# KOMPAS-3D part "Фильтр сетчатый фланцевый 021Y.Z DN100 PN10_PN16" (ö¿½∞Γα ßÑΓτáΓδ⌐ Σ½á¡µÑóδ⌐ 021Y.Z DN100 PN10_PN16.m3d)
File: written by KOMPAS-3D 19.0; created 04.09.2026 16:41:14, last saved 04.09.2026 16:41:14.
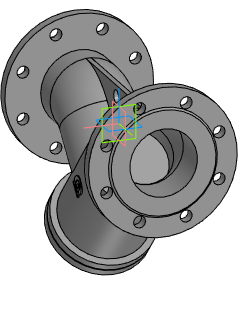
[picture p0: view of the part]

Document properties: Автор: Энергия; Полное имя файла: Z:\3.Личные\sachek\Dendor\_3D для проектировщиков\8.1 Фильтр сетчатый 021Y.Z\021Y.Z_STP\Фильтр сетчатый фланцевый 021Y.Z DN100 PN10_PN16.m3d

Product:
- Part/product: Фильтр сетчатый фланцевый 021Y.Z DN100 PN10_PN16

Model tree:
1. Операция без истории:1  (labels: Фильтр сетчатый фланцевый 021Y.Z DN100 PN10_PN16)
